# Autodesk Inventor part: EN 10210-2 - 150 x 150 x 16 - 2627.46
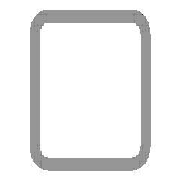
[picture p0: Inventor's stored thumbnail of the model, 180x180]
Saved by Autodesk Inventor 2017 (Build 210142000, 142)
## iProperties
Created: 2017-11
Part Number: EN 10210-2 - 150 x 150 x 16 - 2627.46
Material: Steel, Mild
Description: Tube
Document SubType Name: Modeling
Standard: DIN
Designer: iusti
Standard Revision: 2006-07
Standards Organization: DIN
Language: en-US
Size Designation: 150 x 150 x 16
Categories: <MemberInstance><Categories><Category DisplayName="Structural Shapes" InternalName="089c4875-fa83-4c05-b084-43b9cc11f5ed" Mnemonic="GRDR"><CategoryParameter Dis
Stock Number: 150 x 150 x 16
Density: 7.85 g/cm^3
Appearance: Semi-Polished
_CCFamilyMember: 70
_CCFamilyDisplayName: DIN EN 10210-2 (Square) - Tube — Sizes in parentheses have been withdrawn
_FrameMemberDoc: Frame Member File
_Version: 15.0.0
_GetPNFromCC: 1
IsCustomPart: 1
Author: iusti
G_L: 2627.460 mm
G_W: 150.000 mm
G_H: 150.000 mm
+78899DAD-F749-4824-914A-392FEC18B06A+CUTDETAIL1: Cut
+1A619B89-A6BD-4C44-B3B1-1A5EED163B0B+CUTDETAIL2: Cut
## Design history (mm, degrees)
node "Start plane"
node "End plane"
sketch "Sketch"
  geometry: L1 (-75, -51)-(-75, 51); L2 (-51, 75)-(51, 75); L3 (75, 51)-(75, -51); L4 (51, -75)-(-51, -75); L5 (-43, 59)-(43, 59); L6 (59, 43)-(59, -43); L7 (43, -59)-(-43, -59); L8 (-59, -43)-(-59, 43); L9 (0, 111.959)-(0, -111.959) reference; L10 (-111.959, 0)-(111.959, 0) reference; A1 r 24 centre (-51, -51) between (-75, -51) and (-51, -75); A2 r 24 centre (-51, 51) between (-51, 75) and (-75, 51); A3 r 24 centre (51, 51) between (75, 51) and (51, 75); A4 r 24 centre (51, -51) between (51, -75) and (75, -51); A5 r 16 centre (-43, -43) between (-59, -43) and (-43, -59); A6 r 16 centre (-43, 43) between (-43, 59) and (-59, 43); A7 r 16 centre (43, 43) between (59, 43) and (43, 59); A8 r 16 centre (43, -43) between (43, -59) and (59, -43)
  constraints: 16 end point, 16 point on circle, 16 tangent, 8 centre point, 6 equal radius, 4 parallel, 2 perpendicular, 2 other
  dimensions: "d7" = 24 radius of A1 (= G_IR); "d10" = 150 distance between parallel lines of L2 L4 (= G_H); "d11" = 150 distance between parallel lines of L1 L3 (= G_W); "d12" = 16 distance between parallel lines of L3 L6 (= G_T); "d15" = 75 distance between parallel lines of L2 L10 (= 0.5 x d10); "d16" = 75 distance between parallel lines of L9 L3 (= 0.5 x d11); "d19" = 16 radius of A5 (= G_T); "d20" = 16 distance between parallel lines of L4 L7 (= G_T)
extrude "Body" new body sketch "Sketch" stored distance "d3" = 2627.46034 (= G_L); taper "d4" = 0 deg
node "Driven Length"
  sketch "Sketch3"
    geometry: L1 (0, 0)-(10, 0) reference
    constraints: 2 end point, 1 horizontal
  workplane "Work Plane3"
  sketch "Sketch4"
    geometry: L1 (-2, -92.902)-(12, -92.902) reference; L2 (-2, 2534.559)-(12, 2534.559) reference
    dimensions: "d18" = 2627.46034 distance between parallel lines of L1 L2 (derived)
workplane "Work Plane4"
split "Split1"
workplane "Work Plane5"
split "Split2"
body "Solid1"
other parameters: "G_W" = 150 [user parameter; used in 1 equation term], "G_H" = 150 [user parameter; used in 1 equation term], "G_T" = 16 [user parameter; used in 3 equation terms], "G_IR" = 24 [user parameter; used in 1 equation term], "G_L" = 2627.46034 (= d18) [user parameter; used in 1 equation term], "G_OFFSET_START" = 92.90179 [user parameter; used in 1 equation term], "G_OFFSET_END" = -35.84222 [user parameter; used in 1 equation term], "d13" = -92.90179 (= -G_OFFSET_START), "d14" = 2534.55856 (= G_OFFSET_END + B_L), "B_L" = 2570.40077 [user parameter; used in 1 equation term], "d17" = 90 deg
